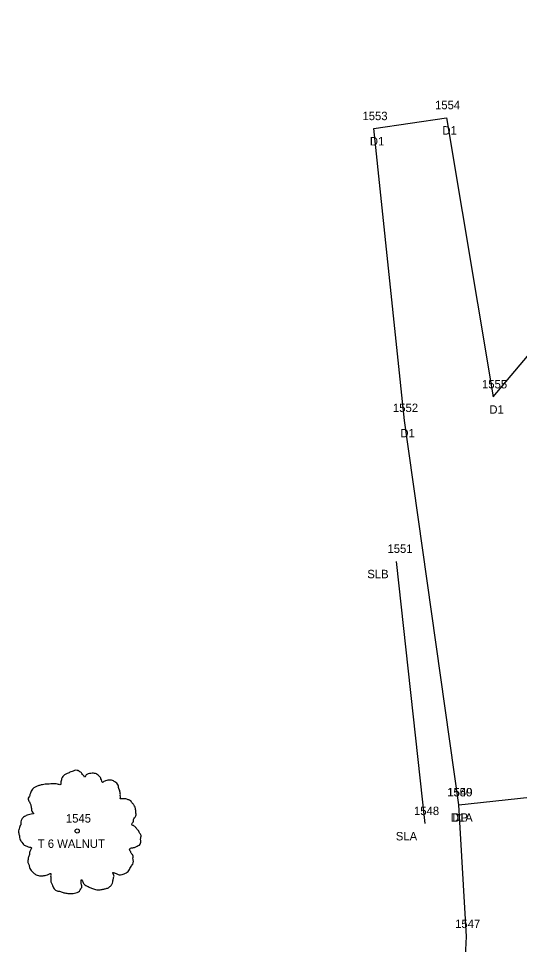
# Model space of a CAD drawing. Extents: x 1964982 to 1970452, y 1116335 to 1119906.
# Drawn here: x 1966525.9 to 1966585.2, y 1117418.7 to 1117528.3 of the extents above; entities that cross this region are included whole.
import ezdxf

# ---------------------------------------------------------------- set-up
doc = ezdxf.new("R2010")
doc.units = 0
for name, color, linetype in [('RD_EX_Driveway', 7, 'Continuous'), ('RD_EX_Driveway_txCode', 7, 'Continuous'), ('RD_EX_VEG', 7, 'Continuous'), ('RD_EX_VEG_txCode', 7, 'Continuous'), ('RD_SMD_Locator', 7, 'Continuous')]:
    doc.layers.add(name, color=color, linetype=linetype)

msp = doc.modelspace()

# ---------------------------------------------------------------- linework, layer by layer
at = {"layer": 'RD_EX_Driveway'}
for points in [[(1966578.03, 1117435.24), (1966571.58, 1117480.75), (1966567.97, 1117515.31), (1966576.56, 1117516.6), (1966582.11, 1117483.55), (1966603.62, 1117509.1), (1966634.75, 1117528.34), (1966662.08, 1117526.43), (1966689.52, 1117514.66), (1966711.52, 1117497.72), (1966730.01, 1117478.51), (1966744.03, 1117462.69), (1966734.11, 1117458.19)], [(1966578.39, 1117408.59), (1966578.94, 1117419.65), (1966578.03, 1117435.24), (1966589.34, 1117436.48), (1966594.39, 1117424.44), (1966597.46, 1117418.81), (1966604.53, 1117414.06)]]:
    msp.add_lwpolyline(points, dxfattribs=at)
at = {"layer": 'RD_EX_VEG'}
msp.add_line((1966574.06, 1117433.03), (1966570.65, 1117464.07), dxfattribs=at)
for centre, radius in [((1966532.85, 1117432.14), 0.25), ((1966532.85, 1117432.14), 0.25), ((1966532.84, 1117432.12), 0.0001), ((1966532.84, 1117432.12), 0.0001)]:
    msp.add_circle(centre, radius, dxfattribs=at)
for points in [[(1966532.98, 1117439.3), (1966532.68, 1117439.33), (1966532.36, 1117439.23), (1966532.11, 1117439.13), (1966531.88, 1117439.05), (1966531.66, 1117438.95), (1966531.36, 1117438.78), (1966531.13, 1117438.58), (1966531.01, 1117438.33), (1966530.96, 1117438.1), (1966530.91, 1117437.83), (1966530.91, 1117437.65), (1966530.78, 1117437.63), (1966530.63, 1117437.65), (1966530.38, 1117437.73), (1966530.13, 1117437.73), (1966529.89, 1117437.73), (1966529.54, 1117437.7), (1966529.19, 1117437.7), (1966528.91, 1117437.65), (1966528.59, 1117437.6), (1966528.21, 1117437.48), (1966527.86, 1117437.35), (1966527.56, 1117437.1), (1966527.31, 1117436.63), (1966527.19, 1117436.28), (1966527.04, 1117436.03), (1966527.19, 1117435.58), (1966527.36, 1117435.23), (1966527.39, 1117435.03), (1966527.46, 1117434.61), (1966527.56, 1117434.38), (1966527.69, 1117434.18), (1966527.61, 1117434.16), (1966527.24, 1117434.11), (1966526.94, 1117434.01), (1966526.51, 1117433.78), (1966526.29, 1117433.56), (1966526.19, 1117433.23), (1966526.16, 1117432.88), (1966526.06, 1117432.68), (1966525.99, 1117432.41), (1966525.96, 1117432.33), (1966525.91, 1117432.01), (1966526.01, 1117431.56), (1966526.04, 1117431.21), (1966526.16, 1117430.98), (1966526.31, 1117430.81), (1966526.49, 1117430.56), (1966526.89, 1117430.33), (1966527.21, 1117430.23), (1966527.41, 1117430.21), (1966527.24, 1117429.71), (1966527.19, 1117429.36), (1966527.06, 1117428.96), (1966527.06, 1117428.88), (1966527.01, 1117428.41), (1966527.16, 1117428.08), (1966527.24, 1117427.71), (1966527.41, 1117427.48), (1966527.69, 1117427.18), (1966528.01, 1117426.96), (1966528.51, 1117426.83), (1966528.91, 1117426.86), (1966529.49, 1117427.03), (1966529.74, 1117427.11), (1966529.71, 1117426.93), (1966529.74, 1117426.56), (1966529.74, 1117426.13), (1966529.89, 1117425.81), (1966529.99, 1117425.53), (1966530.13, 1117425.28), (1966530.46, 1117425.06), (1966530.86, 1117424.98), (1966531.28, 1117424.83), (1966531.73, 1117424.76), (1966532.23, 1117424.73), (1966532.83, 1117424.88), (1966533.11, 1117425.01), (1966533.21, 1117425.18), (1966533.41, 1117425.56), (1966533.36, 1117425.78), (1966533.38, 1117426.38), (1966533.48, 1117426.21), (1966533.66, 1117425.86), (1966534.16, 1117425.56), (1966534.56, 1117425.38), (1966535.03, 1117425.23), (1966535.33, 1117425.16), (1966535.81, 1117425.23), (1966536.18, 1117425.31), (1966536.56, 1117425.43), (1966536.86, 1117425.71), (1966537.03, 1117425.98), (1966537.08, 1117426.26), (1966537.16, 1117426.63), (1966537.21, 1117426.81)], [(1966532.98, 1117439.3), (1966532.68, 1117439.33), (1966532.36, 1117439.23), (1966532.11, 1117439.13), (1966531.88, 1117439.05), (1966531.66, 1117438.95), (1966531.36, 1117438.78), (1966531.13, 1117438.58), (1966531.01, 1117438.33), (1966530.96, 1117438.1), (1966530.91, 1117437.83), (1966530.91, 1117437.65), (1966530.78, 1117437.63), (1966530.63, 1117437.65), (1966530.38, 1117437.73), (1966530.13, 1117437.73), (1966529.89, 1117437.73), (1966529.54, 1117437.7), (1966529.19, 1117437.7), (1966528.91, 1117437.65), (1966528.59, 1117437.6), (1966528.21, 1117437.48), (1966527.86, 1117437.35), (1966527.56, 1117437.1), (1966527.31, 1117436.63), (1966527.19, 1117436.28), (1966527.04, 1117436.03), (1966527.19, 1117435.58), (1966527.36, 1117435.23), (1966527.39, 1117435.03), (1966527.46, 1117434.61), (1966527.56, 1117434.38), (1966527.69, 1117434.18), (1966527.61, 1117434.16), (1966527.24, 1117434.11), (1966526.94, 1117434.01), (1966526.51, 1117433.78), (1966526.29, 1117433.56), (1966526.19, 1117433.23), (1966526.16, 1117432.88), (1966526.06, 1117432.68), (1966525.99, 1117432.41), (1966525.96, 1117432.33), (1966525.91, 1117432.01), (1966526.01, 1117431.56), (1966526.04, 1117431.21), (1966526.16, 1117430.98), (1966526.31, 1117430.81), (1966526.49, 1117430.56), (1966526.89, 1117430.33), (1966527.21, 1117430.23), (1966527.41, 1117430.21), (1966527.24, 1117429.71), (1966527.19, 1117429.36), (1966527.06, 1117428.96), (1966527.06, 1117428.88), (1966527.01, 1117428.41), (1966527.16, 1117428.08), (1966527.24, 1117427.71), (1966527.41, 1117427.48), (1966527.69, 1117427.18), (1966528.01, 1117426.96), (1966528.51, 1117426.83), (1966528.91, 1117426.86), (1966529.49, 1117427.03), (1966529.74, 1117427.11), (1966529.71, 1117426.93), (1966529.74, 1117426.56), (1966529.74, 1117426.13), (1966529.89, 1117425.81), (1966529.99, 1117425.53), (1966530.13, 1117425.28), (1966530.46, 1117425.06), (1966530.86, 1117424.98), (1966531.28, 1117424.83), (1966531.73, 1117424.76), (1966532.23, 1117424.73), (1966532.83, 1117424.88), (1966533.11, 1117425.01), (1966533.21, 1117425.18), (1966533.41, 1117425.56), (1966533.36, 1117425.78), (1966533.38, 1117426.38), (1966533.48, 1117426.21), (1966533.66, 1117425.86), (1966534.16, 1117425.56), (1966534.56, 1117425.38), (1966535.03, 1117425.23), (1966535.33, 1117425.16), (1966535.81, 1117425.23), (1966536.18, 1117425.31), (1966536.56, 1117425.43), (1966536.86, 1117425.71), (1966537.03, 1117425.98), (1966537.08, 1117426.26), (1966537.16, 1117426.63), (1966537.21, 1117426.81)], [(1966537.21, 1117426.81), (1966537.13, 1117426.98), (1966537.08, 1117427.23), (1966537.16, 1117427.21), (1966537.33, 1117427.16), (1966537.61, 1117427.03), (1966537.83, 1117426.96), (1966538.16, 1117426.98), (1966538.43, 1117427.08), (1966538.88, 1117427.36), (1966539.16, 1117427.83), (1966539.43, 1117428.23), (1966539.51, 1117428.56), (1966539.46, 1117428.78), (1966539.43, 1117429.28), (1966539.23, 1117429.53), (1966539.18, 1117429.66), (1966539.08, 1117430.06), (1966539.16, 1117430.11), (1966539.43, 1117430.16), (1966539.81, 1117430.28), (1966540.08, 1117430.41), (1966540.31, 1117430.58), (1966540.38, 1117430.81), (1966540.36, 1117431.21), (1966540.41, 1117431.61), (1966540.33, 1117431.76), (1966540.23, 1117431.91), (1966540.16, 1117432.11), (1966540.01, 1117432.26), (1966539.91, 1117432.41), (1966539.81, 1117432.51), (1966539.68, 1117432.66), (1966539.51, 1117432.78), (1966539.36, 1117432.83), (1966539.31, 1117432.98), (1966539.46, 1117433.18), (1966539.51, 1117433.28), (1966539.53, 1117433.51), (1966539.76, 1117433.86), (1966539.81, 1117434.26), (1966539.76, 1117434.68), (1966539.71, 1117434.96), (1966539.56, 1117435.23), (1966539.36, 1117435.48), (1966539.23, 1117435.66), (1966539.06, 1117435.78), (1966538.73, 1117435.91), (1966538.48, 1117435.96), (1966538.13, 1117435.96), (1966537.93, 1117436.01), (1966537.96, 1117436.06), (1966537.96, 1117436.2), (1966537.96, 1117436.48), (1966537.88, 1117436.93), (1966537.73, 1117437.43), (1966537.73, 1117437.45), (1966537.63, 1117437.7), (1966537.41, 1117437.9), (1966537.23, 1117438), (1966537.03, 1117438.13), (1966536.78, 1117438.15), (1966536.48, 1117438.15), (1966536.21, 1117438.1), (1966536.01, 1117438), (1966535.83, 1117437.88), (1966535.76, 1117438.03), (1966535.66, 1117438.33), (1966535.61, 1117438.48), (1966535.46, 1117438.65), (1966535.23, 1117438.85), (1966534.78, 1117438.98), (1966534.16, 1117438.9), (1966533.86, 1117438.7), (1966533.71, 1117438.53), (1966533.66, 1117438.65), (1966533.46, 1117438.85), (1966533.36, 1117439.03), (1966533.18, 1117439.15), (1966533.03, 1117439.25), (1966532.93, 1117439.3)], [(1966537.21, 1117426.81), (1966537.13, 1117426.98), (1966537.08, 1117427.23), (1966537.16, 1117427.21), (1966537.33, 1117427.16), (1966537.61, 1117427.03), (1966537.83, 1117426.96), (1966538.16, 1117426.98), (1966538.43, 1117427.08), (1966538.88, 1117427.36), (1966539.16, 1117427.83), (1966539.43, 1117428.23), (1966539.51, 1117428.56), (1966539.46, 1117428.78), (1966539.43, 1117429.28), (1966539.23, 1117429.53), (1966539.18, 1117429.66), (1966539.08, 1117430.06), (1966539.16, 1117430.11), (1966539.43, 1117430.16), (1966539.81, 1117430.28), (1966540.08, 1117430.41), (1966540.31, 1117430.58), (1966540.38, 1117430.81), (1966540.36, 1117431.21), (1966540.41, 1117431.61), (1966540.33, 1117431.76), (1966540.23, 1117431.91), (1966540.16, 1117432.11), (1966540.01, 1117432.26), (1966539.91, 1117432.41), (1966539.81, 1117432.51), (1966539.68, 1117432.66), (1966539.51, 1117432.78), (1966539.36, 1117432.83), (1966539.31, 1117432.98), (1966539.46, 1117433.18), (1966539.51, 1117433.28), (1966539.53, 1117433.51), (1966539.76, 1117433.86), (1966539.81, 1117434.26), (1966539.76, 1117434.68), (1966539.71, 1117434.96), (1966539.56, 1117435.23), (1966539.36, 1117435.48), (1966539.23, 1117435.66), (1966539.06, 1117435.78), (1966538.73, 1117435.91), (1966538.48, 1117435.96), (1966538.13, 1117435.96), (1966537.93, 1117436.01), (1966537.96, 1117436.06), (1966537.96, 1117436.2), (1966537.96, 1117436.48), (1966537.88, 1117436.93), (1966537.73, 1117437.43), (1966537.73, 1117437.45), (1966537.63, 1117437.7), (1966537.41, 1117437.9), (1966537.23, 1117438), (1966537.03, 1117438.13), (1966536.78, 1117438.15), (1966536.48, 1117438.15), (1966536.21, 1117438.1), (1966536.01, 1117438), (1966535.83, 1117437.88), (1966535.76, 1117438.03), (1966535.66, 1117438.33), (1966535.61, 1117438.48), (1966535.46, 1117438.65), (1966535.23, 1117438.85), (1966534.78, 1117438.98), (1966534.16, 1117438.9), (1966533.86, 1117438.7), (1966533.71, 1117438.53), (1966533.66, 1117438.65), (1966533.46, 1117438.85), (1966533.36, 1117439.03), (1966533.18, 1117439.15), (1966533.03, 1117439.25), (1966532.93, 1117439.3)]]:
    msp.add_spline(points, degree=3, dxfattribs=at)
at = {"layer": 'RD_SMD_Locator'}
for centre in [(1966576.56, 1117516.6), (1966576.56, 1117516.6), (1966567.97, 1117515.31), (1966567.97, 1117515.31), (1966582.11, 1117483.55), (1966582.11, 1117483.55), (1966571.58, 1117480.75), (1966571.58, 1117480.75), (1966570.65, 1117464.07), (1966570.65, 1117464.07), (1966578.03, 1117435.24), (1966578.03, 1117435.24), (1966578.03, 1117435.24), (1966578.03, 1117435.24), (1966574.06, 1117433.03), (1966574.06, 1117433.03), (1966578.94, 1117419.65), (1966578.94, 1117419.65)]:
    msp.add_circle(centre, 0.001, dxfattribs=at)

# ---------------------------------------------------------------- texts
at = {"layer": 'RD_EX_Driveway_txCode'}
for s, p in [('1554', (1966575.21, 1117517.6)), ('1554', (1966575.21, 1117517.6)), ('1553', (1966566.62, 1117516.31)), ('1553', (1966566.62, 1117516.31)), ('D1', (1966576.08, 1117514.6)), ('D1', (1966576.08, 1117514.6)), ('D1', (1966567.5, 1117513.31)), ('D1', (1966567.5, 1117513.31)), ('1555', (1966580.77, 1117484.55)), ('1555', (1966580.77, 1117484.55)), ('1552', (1966570.23, 1117481.75)), ('1552', (1966570.23, 1117481.75)), ('D1', (1966581.64, 1117481.55)), ('D1', (1966581.64, 1117481.55)), ('D1', (1966571.11, 1117478.75)), ('D1', (1966571.11, 1117478.75)), ('1550', (1966576.64, 1117436.24)), ('1550', (1966576.64, 1117436.24)), ('1549', (1966576.68, 1117436.24)), ('1549', (1966576.68, 1117436.24)), ('D1A', (1966577.07, 1117433.24)), ('D1A', (1966577.07, 1117433.24)), ('DP', (1966577.25, 1117433.24)), ('DP', (1966577.25, 1117433.24)), ('1547', (1966577.59, 1117420.65)), ('1547', (1966577.59, 1117420.65))]:
    msp.add_text(s, height=1, dxfattribs=at).set_placement(p)
at = {"layer": 'RD_EX_VEG_txCode'}
for s, p in [('1551', (1966569.58, 1117465.07)), ('1551', (1966569.58, 1117465.07)), ('SLB', (1966567.19, 1117462.07)), ('SLB', (1966567.19, 1117462.07)), ('1548', (1966572.72, 1117434.03)), ('1548', (1966572.72, 1117434.03)), ('1545', (1966531.51, 1117433.14)), ('1545', (1966531.51, 1117433.14)), ('T 6 WALNUT', (1966528.18, 1117430.14)), ('T 6 WALNUT', (1966528.18, 1117430.14)), ('SLA', (1966570.57, 1117431.03)), ('SLA', (1966570.57, 1117431.03))]:
    msp.add_text(s, height=1, dxfattribs=at).set_placement(p)

doc.saveas('drawing.dxf')
